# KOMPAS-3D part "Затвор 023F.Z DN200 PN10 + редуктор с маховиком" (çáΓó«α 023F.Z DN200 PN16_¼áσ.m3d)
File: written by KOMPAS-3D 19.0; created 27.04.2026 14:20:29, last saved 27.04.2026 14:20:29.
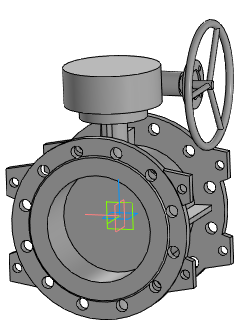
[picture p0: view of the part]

Document properties: Полное имя файла: ..\..\Затвор 023F.Z DN200-DN1600_с маховиком\Затвор 023F.Z DN200 PN16 + редуктор с маховиком.a3d

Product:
- Part/product: Затвор 023F.Z DN200 PN10 + редуктор с маховиком
    Масса: 59.5013

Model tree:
1. Операция без истории:1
